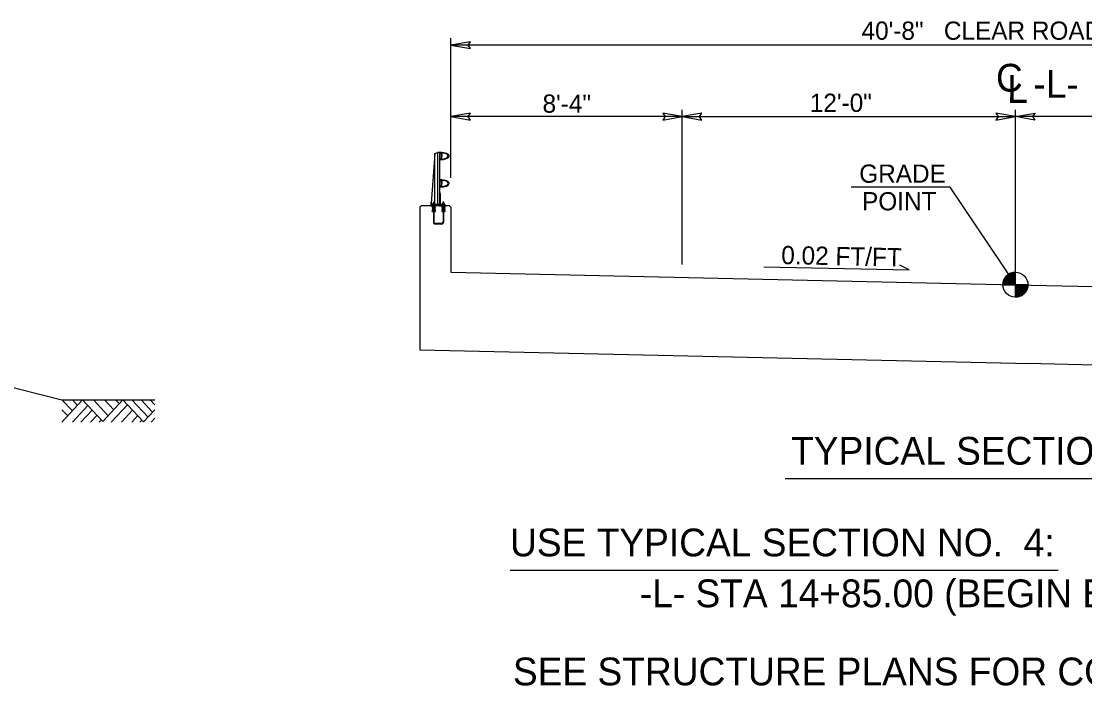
# Model space of a CAD drawing. Extents: x 1901984 to 1902132, y 194049 to 194156.
# Drawn here: x 1902050.33 to 1902088.64, y 194131.76 to 194155.68 of the extents above; entities that cross this region are included whole.
import ezdxf

# ---------------------------------------------------------------- set-up
doc = ezdxf.new("R2010")
doc.units = 0
for name, color, linetype in [('Old_Level_1', 7, 'Continuous'), ('Old_Level_11', 7, 'Continuous'), ('Old_Level_2', 7, 'Continuous'), ('Old_Level_3', 7, 'Continuous'), ('Scratch_Level_3', 7, 'Continuous'), ('Sheet PE Seal Cell', 7, 'Continuous')]:
    doc.layers.add(name, color=color, linetype=linetype)

# ---------------------------------------------------------------- blocks, each defined once
blk = doc.blocks.new('TERMINATOR')
at = {"layer": 'Scratch_Level_3'}
blk.add_lwpolyline([(-0.469, 0.081), (0, 0), (-0.471, -0.083), (-0.411, 0)], close=True, dxfattribs=at)

msp = doc.modelspace()

# ---------------------------------------------------------------- linework, layer by layer
at = {"layer": 'Old_Level_1'}
for p, q in [((1902065.811, 194150.049), (1902065.811, 194155.073)), ((1902106.478, 194154.823), (1902065.811, 194154.823)), ((1902074.144, 194146.923), (1902074.144, 194152.498)), ((1902086.144, 194146.196), (1902086.144, 194152.498)), ((1902074.144, 194152.249), (1902065.811, 194152.249)), ((1902074.144, 194152.248), (1902086.144, 194152.248)), ((1902098.144, 194152.248), (1902086.144, 194152.248)), ((1902064.693, 194146.673), (1902064.693, 194143.855)), ((1902065.811, 194146.648), (1902086.144, 194146.196)), ((1902077.081, 194146.843), (1902082.314, 194146.738)), ((1902082.314, 194146.738), (1902081.981, 194146.905)), ((1902086.144, 194146.196), (1902086.144, 194146.646)), ((1902085.694, 194146.196), (1902086.144, 194146.196)), ((1902086.145, 194145.746), (1902086.144, 194146.196)), ((1902086.594, 194146.196), (1902086.144, 194146.196)), ((1902086.144, 194146.196), (1902086.145, 194145.746)), ((1902086.144, 194146.196), (1902106.478, 194145.745)), ((1902039.554, 194145.116), (1902051.797, 194142.055)), ((1902064.693, 194143.855), (1902086.689, 194143.366)), ((1902086.563, 194143.369), (1902107.596, 194142.901))]:
    msp.add_line(p, q, dxfattribs=at)
for points in [[(1902085.978, 194146.614), (1902085.978, 194146.196)], [(1902085.987, 194146.618), (1902085.987, 194146.196)], [(1902085.996, 194146.621), (1902085.996, 194146.196)], [(1902086.005, 194146.624), (1902086.005, 194146.196)], [(1902086.014, 194146.627), (1902086.014, 194146.196)], [(1902086.023, 194146.629), (1902086.023, 194146.196)], [(1902086.032, 194146.632), (1902086.032, 194146.196)], [(1902086.041, 194146.634), (1902086.041, 194146.196)], [(1902086.05, 194146.636), (1902086.05, 194146.196)], [(1902086.059, 194146.638), (1902086.059, 194146.196)], [(1902086.068, 194146.64), (1902086.068, 194146.196)], [(1902086.077, 194146.641), (1902086.077, 194146.196)], [(1902086.086, 194146.642), (1902086.086, 194146.196)], [(1902086.095, 194146.643), (1902086.095, 194146.196)], [(1902086.104, 194146.644), (1902086.104, 194146.196)], [(1902086.113, 194146.645), (1902086.113, 194146.196)], [(1902086.122, 194146.645), (1902086.122, 194146.196)], [(1902086.131, 194146.646), (1902086.131, 194146.196)], [(1902086.14, 194146.646), (1902086.14, 194146.646), (1902086.14, 194146.196)], [(1902085.699, 194146.26), (1902085.699, 194146.196)], [(1902085.708, 194146.306), (1902085.708, 194146.196)], [(1902085.717, 194146.337), (1902085.717, 194146.196)], [(1902085.726, 194146.362), (1902085.726, 194146.196)], [(1902085.735, 194146.383), (1902085.735, 194146.196)], [(1902085.744, 194146.402), (1902085.744, 194146.196)], [(1902085.753, 194146.418), (1902085.753, 194146.196)], [(1902085.762, 194146.433), (1902085.762, 194146.196)], [(1902085.771, 194146.447), (1902085.771, 194146.196)], [(1902085.78, 194146.46), (1902085.78, 194146.196)], [(1902085.789, 194146.472), (1902085.789, 194146.196)], [(1902085.798, 194146.483), (1902085.798, 194146.196)], [(1902085.807, 194146.494), (1902085.807, 194146.196)], [(1902085.816, 194146.504), (1902085.816, 194146.196)], [(1902085.825, 194146.513), (1902085.825, 194146.196)], [(1902085.834, 194146.522), (1902085.834, 194146.196)], [(1902085.843, 194146.53), (1902085.843, 194146.196)], [(1902085.852, 194146.538), (1902085.852, 194146.196)], [(1902085.861, 194146.546), (1902085.861, 194146.196)], [(1902085.87, 194146.553), (1902085.87, 194146.196)], [(1902085.879, 194146.559), (1902085.879, 194146.196)], [(1902085.888, 194146.566), (1902085.888, 194146.196)], [(1902085.897, 194146.572), (1902085.897, 194146.196)], [(1902085.906, 194146.578), (1902085.906, 194146.196)], [(1902085.915, 194146.583), (1902085.915, 194146.196)], [(1902085.924, 194146.588), (1902085.924, 194146.196)], [(1902085.933, 194146.593), (1902085.933, 194146.196)], [(1902085.942, 194146.598), (1902085.942, 194146.196)], [(1902085.951, 194146.602), (1902085.951, 194146.196)], [(1902085.96, 194146.606), (1902085.96, 194146.196)], [(1902085.969, 194146.61), (1902085.969, 194146.196)], [(1902086.151, 194146.196), (1902086.151, 194145.746), (1902086.151, 194145.746)], [(1902086.16, 194146.196), (1902086.16, 194145.746)], [(1902086.169, 194146.196), (1902086.169, 194145.747)], [(1902086.178, 194146.196), (1902086.178, 194145.747)], [(1902086.187, 194146.196), (1902086.187, 194145.748)], [(1902086.196, 194146.196), (1902086.196, 194145.749)], [(1902086.205, 194146.196), (1902086.205, 194145.75)], [(1902086.214, 194146.196), (1902086.214, 194145.752)], [(1902086.223, 194146.196), (1902086.223, 194145.753)], [(1902086.232, 194146.196), (1902086.232, 194145.755)], [(1902086.241, 194146.196), (1902086.241, 194145.757)], [(1902086.25, 194146.196), (1902086.25, 194145.759)], [(1902086.259, 194146.196), (1902086.259, 194145.761)], [(1902086.268, 194146.196), (1902086.268, 194145.764)], [(1902086.277, 194146.196), (1902086.277, 194145.766)], [(1902086.286, 194146.196), (1902086.286, 194145.769)], [(1902086.295, 194146.196), (1902086.295, 194145.772)], [(1902086.304, 194146.196), (1902086.304, 194145.775)], [(1902086.313, 194146.196), (1902086.313, 194145.779)], [(1902086.322, 194146.196), (1902086.322, 194145.783)], [(1902086.331, 194146.196), (1902086.331, 194145.787)], [(1902086.34, 194146.196), (1902086.34, 194145.791)], [(1902086.349, 194146.196), (1902086.349, 194145.795)], [(1902086.358, 194146.196), (1902086.358, 194145.8)], [(1902086.367, 194146.196), (1902086.367, 194145.805)], [(1902086.376, 194146.196), (1902086.376, 194145.81)], [(1902086.385, 194146.196), (1902086.385, 194145.816)], [(1902086.394, 194146.196), (1902086.394, 194145.822)], [(1902086.403, 194146.196), (1902086.403, 194145.828)], [(1902086.412, 194146.196), (1902086.412, 194145.834)], [(1902086.421, 194146.196), (1902086.421, 194145.841)], [(1902086.43, 194146.196), (1902086.43, 194145.848)], [(1902086.439, 194146.196), (1902086.439, 194145.856)], [(1902086.448, 194146.196), (1902086.448, 194145.864)], [(1902086.457, 194146.196), (1902086.457, 194145.872)], [(1902086.466, 194146.196), (1902086.466, 194145.881)], [(1902086.475, 194146.196), (1902086.475, 194145.891)], [(1902086.484, 194146.196), (1902086.484, 194145.901)], [(1902086.493, 194146.196), (1902086.493, 194145.912)], [(1902086.502, 194146.196), (1902086.502, 194145.923)], [(1902086.511, 194146.196), (1902086.511, 194145.935)], [(1902086.52, 194146.196), (1902086.52, 194145.948)], [(1902086.529, 194146.196), (1902086.529, 194145.962)], [(1902086.538, 194146.196), (1902086.538, 194145.978)], [(1902086.547, 194146.196), (1902086.547, 194145.995)], [(1902086.556, 194146.196), (1902086.556, 194146.014)], [(1902086.565, 194146.196), (1902086.565, 194146.035)], [(1902086.574, 194146.196), (1902086.574, 194146.062)], [(1902086.583, 194146.196), (1902086.583, 194146.094)], [(1902086.592, 194146.196), (1902086.592, 194146.147)], [(1902051.797, 194142.055), (1902055.139, 194142.055)]]:
    msp.add_lwpolyline(points, dxfattribs=at)
msp.add_circle((1902086.145, 194146.196), 0.45, dxfattribs=at)
for start, end in [(90.0095, 180.0095), (270.0095, 0.0095)]:
    msp.add_arc((1902086.145, 194146.196), 0.45, start, end, dxfattribs=at)
at = {"layer": 'Old_Level_11'}
for p, q in [((1902051.797, 194142.055), (1902052.172, 194141.652)), ((1902051.797, 194141.25), (1902052.539, 194142.047)), ((1902052.172, 194142.055), (1902052.359, 194141.854)), ((1902052.539, 194142.047), (1902053.263, 194141.268)), ((1902052.93, 194142.055), (1902053.463, 194141.482)), ((1902053.263, 194141.268), (1902053.994, 194142.054)), ((1902053.328, 194142.055), (1902053.661, 194141.696)), ((1902053.73, 194142.055), (1902053.863, 194141.912)), ((1902053.994, 194142.054), (1902054.735, 194141.258)), ((1902054.316, 194142.055), (1902054.896, 194141.432)), ((1902054.649, 194142.055), (1902055.063, 194141.611)), ((1902054.969, 194142.055), (1902055.139, 194141.872)), ((1902051.797, 194141.693), (1902052.003, 194141.471)), ((1902052.171, 194141.25), (1902052.725, 194141.846)), ((1902052.48, 194141.25), (1902052.881, 194141.679)), ((1902053.573, 194141.25), (1902054.159, 194141.878)), ((1902053.943, 194141.25), (1902054.343, 194141.679)), ((1902054.735, 194141.258), (1902055.139, 194141.693)), ((1902052.827, 194141.25), (1902053.054, 194141.493)), ((1902053.138, 194141.25), (1902053.209, 194141.326)), ((1902054.309, 194141.25), (1902054.526, 194141.483)), ((1902054.604, 194141.25), (1902054.673, 194141.324)), ((1902055.005, 194141.25), (1902055.139, 194141.393)), ((1902077.852, 194139.224), (1902094.478, 194139.224)), ((1902067.938, 194135.923), (1902087.682, 194135.923))]:
    msp.add_line(p, q, dxfattribs=at)
at = {"layer": 'Old_Level_3'}
for q in [(1902080.229, 194149.711), (1902086.144, 194146.196)]:
    msp.add_line((1902083.786, 194149.711), q, dxfattribs=at)
at = {"layer": 'Sheet PE Seal Cell'}
for p, q in [((1902065.223, 194150.926), (1902065.092, 194149.117)), ((1902065.223, 194150.926), (1902065.337, 194150.963)), ((1902065.223, 194149.08), (1902065.223, 194150.926)), ((1902065.412, 194150.963), (1902065.337, 194150.963)), ((1902065.337, 194149.08), (1902065.337, 194150.963)), ((1902065.412, 194149.08), (1902065.412, 194150.963)), ((1902065.475, 194150.932), (1902065.475, 194150.83)), ((1902065.475, 194150.727), (1902065.475, 194150.83)), ((1902065.223, 194150.062), (1902065.219, 194150.062)), ((1902065.475, 194149.945), (1902065.475, 194149.843)), ((1902065.475, 194149.74), (1902065.475, 194149.843)), ((1902064.693, 194148.993), (1902064.742, 194149.042)), ((1902064.693, 194148.993), (1902064.693, 194146.673)), ((1902065.762, 194149.042), (1902064.742, 194149.042)), ((1902065.092, 194149.08), (1902065.092, 194149.117)), ((1902065.095, 194149.138), (1902065.095, 194149.171)), ((1902065.235, 194149.006), (1902065.135, 194149.006)), ((1902065.235, 194148.995), (1902065.135, 194148.995)), ((1902065.177, 194148.961), (1902065.135, 194148.961)), ((1902065.177, 194148.95), (1902065.135, 194148.95)), ((1902065.177, 194148.917), (1902065.135, 194148.917)), ((1902065.177, 194148.983), (1902065.157, 194148.983)), ((1902065.177, 194148.972), (1902065.157, 194148.972)), ((1902065.177, 194148.939), (1902065.157, 194148.939)), ((1902065.177, 194148.928), (1902065.157, 194148.928)), ((1902065.164, 194148.996), (1902065.164, 194149.08)), ((1902065.208, 194149.156), (1902065.165, 194149.156)), ((1902065.165, 194149.156), (1902065.165, 194149.12)), ((1902065.193, 194148.984), (1902065.177, 194148.984)), ((1902065.177, 194148.984), (1902065.177, 194148.453)), ((1902065.193, 194148.984), (1902065.193, 194148.453)), ((1902065.213, 194148.983), (1902065.193, 194148.983)), ((1902065.213, 194148.972), (1902065.193, 194148.972)), ((1902065.235, 194148.961), (1902065.193, 194148.961)), ((1902065.235, 194148.95), (1902065.193, 194148.95)), ((1902065.213, 194148.939), (1902065.193, 194148.939)), ((1902065.213, 194148.928), (1902065.193, 194148.928)), ((1902065.235, 194148.917), (1902065.193, 194148.917)), ((1902065.208, 194149.12), (1902065.208, 194149.156)), ((1902065.208, 194148.996), (1902065.208, 194149.08)), ((1902065.584, 194149.006), (1902065.483, 194149.006)), ((1902065.584, 194148.995), (1902065.483, 194148.995)), ((1902065.525, 194148.961), (1902065.483, 194148.961)), ((1902065.525, 194148.95), (1902065.483, 194148.95)), ((1902065.525, 194148.917), (1902065.483, 194148.917)), ((1902065.525, 194148.983), (1902065.506, 194148.983)), ((1902065.525, 194148.972), (1902065.506, 194148.972)), ((1902065.525, 194148.939), (1902065.506, 194148.939)), ((1902065.525, 194148.928), (1902065.506, 194148.928)), ((1902065.512, 194149.006), (1902065.512, 194149.089)), ((1902065.557, 194149.166), (1902065.514, 194149.166)), ((1902065.514, 194149.166), (1902065.514, 194149.13)), ((1902065.525, 194148.984), (1902065.525, 194148.453)), ((1902065.542, 194148.983), (1902065.525, 194148.983)), ((1902065.542, 194148.984), (1902065.542, 194148.453)), ((1902065.562, 194148.983), (1902065.542, 194148.983)), ((1902065.562, 194148.972), (1902065.542, 194148.972)), ((1902065.584, 194148.961), (1902065.542, 194148.961)), ((1902065.584, 194148.95), (1902065.542, 194148.95)), ((1902065.562, 194148.939), (1902065.542, 194148.939)), ((1902065.562, 194148.928), (1902065.542, 194148.928)), ((1902065.584, 194148.917), (1902065.542, 194148.917)), ((1902065.557, 194149.13), (1902065.557, 194149.166)), ((1902065.559, 194149.006), (1902065.559, 194149.089)), ((1902065.762, 194149.042), (1902065.811, 194148.993)), ((1902065.811, 194148.993), (1902065.811, 194146.648)), ((1902065.177, 194148.906), (1902065.135, 194148.906)), ((1902065.177, 194148.873), (1902065.135, 194148.873)), ((1902065.177, 194148.861), (1902065.135, 194148.861)), ((1902065.177, 194148.828), (1902065.135, 194148.828)), ((1902065.177, 194148.817), (1902065.135, 194148.817)), ((1902065.177, 194148.895), (1902065.157, 194148.895)), ((1902065.177, 194148.884), (1902065.157, 194148.884)), ((1902065.177, 194148.85), (1902065.157, 194148.85)), ((1902065.177, 194148.839), (1902065.157, 194148.839)), ((1902065.235, 194148.906), (1902065.193, 194148.906)), ((1902065.213, 194148.895), (1902065.193, 194148.895)), ((1902065.213, 194148.884), (1902065.193, 194148.884)), ((1902065.235, 194148.873), (1902065.193, 194148.873)), ((1902065.235, 194148.861), (1902065.193, 194148.861)), ((1902065.213, 194148.85), (1902065.193, 194148.85)), ((1902065.213, 194148.839), (1902065.193, 194148.839)), ((1902065.235, 194148.828), (1902065.193, 194148.828)), ((1902065.235, 194148.817), (1902065.193, 194148.817)), ((1902065.525, 194148.906), (1902065.483, 194148.906)), ((1902065.525, 194148.873), (1902065.483, 194148.873)), ((1902065.525, 194148.861), (1902065.483, 194148.861)), ((1902065.525, 194148.828), (1902065.483, 194148.828)), ((1902065.525, 194148.817), (1902065.483, 194148.817)), ((1902065.525, 194148.895), (1902065.506, 194148.895)), ((1902065.525, 194148.884), (1902065.506, 194148.884)), ((1902065.525, 194148.85), (1902065.506, 194148.85)), ((1902065.525, 194148.839), (1902065.506, 194148.839)), ((1902065.584, 194148.906), (1902065.542, 194148.906)), ((1902065.562, 194148.895), (1902065.542, 194148.895)), ((1902065.562, 194148.884), (1902065.542, 194148.884)), ((1902065.584, 194148.873), (1902065.542, 194148.873)), ((1902065.584, 194148.861), (1902065.542, 194148.861)), ((1902065.562, 194148.85), (1902065.542, 194148.85)), ((1902065.562, 194148.839), (1902065.542, 194148.839)), ((1902065.584, 194148.828), (1902065.542, 194148.828)), ((1902065.584, 194148.817), (1902065.542, 194148.817)), ((1902065.472, 194148.4), (1902065.247, 194148.4)), ((1902065.472, 194148.383), (1902065.247, 194148.383))]:
    msp.add_line(p, q, dxfattribs=at)
for points in [[(1902065.412, 194150.699), (1902065.412, 194150.748), (1902065.432, 194150.748), (1902065.432, 194150.74), (1902065.431, 194150.74), (1902065.431, 194150.719), (1902065.463, 194150.719), (1902065.467, 194150.751), (1902065.467, 194150.83), (1902065.467, 194150.908), (1902065.463, 194150.94), (1902065.431, 194150.94), (1902065.431, 194150.919), (1902065.432, 194150.919), (1902065.432, 194150.911), (1902065.412, 194150.911), (1902065.412, 194150.96)], [(1902065.412, 194149.712), (1902065.412, 194149.761), (1902065.432, 194149.761), (1902065.432, 194149.753), (1902065.431, 194149.753), (1902065.431, 194149.732), (1902065.463, 194149.732), (1902065.467, 194149.764), (1902065.467, 194149.843), (1902065.467, 194149.921), (1902065.463, 194149.952), (1902065.431, 194149.952), (1902065.431, 194149.932), (1902065.432, 194149.932), (1902065.432, 194149.924), (1902065.412, 194149.924), (1902065.412, 194149.973)], [(1902065.605, 194149.042), (1902065.605, 194149.089), (1902065.431, 194149.089), (1902065.431, 194149.476), (1902065.412, 194149.476), (1902065.412, 194149.08), (1902065.1, 194149.08), (1902065.1, 194149.107), (1902065.092, 194149.107), (1902065.092, 194149.042), (1902065.242, 194149.042), (1902065.242, 194149.068), (1902065.393, 194149.068), (1902065.393, 194149.042), (1902065.605, 194149.042)], [(1902065.135, 194149.006), (1902065.135, 194148.995), (1902065.157, 194148.983), (1902065.157, 194148.972), (1902065.135, 194148.961), (1902065.135, 194148.95), (1902065.157, 194148.939), (1902065.157, 194148.928), (1902065.135, 194148.917), (1902065.135, 194148.906), (1902065.157, 194148.895), (1902065.157, 194148.884), (1902065.135, 194148.873), (1902065.135, 194148.861), (1902065.157, 194148.85), (1902065.157, 194148.839), (1902065.135, 194148.828), (1902065.135, 194148.817)], [(1902065.229, 194149.079), (1902065.229, 194149.088), (1902065.186, 194149.088), (1902065.143, 194149.088), (1902065.143, 194149.079)], [(1902065.218, 194149.088), (1902065.218, 194149.115), (1902065.213, 194149.12), (1902065.16, 194149.12), (1902065.154, 194149.115), (1902065.154, 194149.088), (1902065.218, 194149.088), (1902065.197, 194149.088), (1902065.197, 194149.115), (1902065.202, 194149.12), (1902065.197, 194149.115), (1902065.192, 194149.12), (1902065.181, 194149.12), (1902065.175, 194149.115), (1902065.175, 194149.088), (1902065.175, 194149.115), (1902065.17, 194149.12)], [(1902065.235, 194149.006), (1902065.235, 194148.995), (1902065.213, 194148.983), (1902065.213, 194148.972), (1902065.235, 194148.961), (1902065.235, 194148.95), (1902065.213, 194148.939), (1902065.213, 194148.928), (1902065.235, 194148.917), (1902065.235, 194148.906), (1902065.213, 194148.895), (1902065.213, 194148.884), (1902065.235, 194148.873), (1902065.235, 194148.861), (1902065.213, 194148.85), (1902065.213, 194148.839), (1902065.235, 194148.828), (1902065.235, 194148.817)], [(1902065.483, 194149.006), (1902065.483, 194148.995), (1902065.506, 194148.983), (1902065.506, 194148.972), (1902065.483, 194148.961), (1902065.483, 194148.95), (1902065.506, 194148.939), (1902065.506, 194148.928), (1902065.483, 194148.917), (1902065.483, 194148.906), (1902065.506, 194148.895), (1902065.506, 194148.884), (1902065.483, 194148.873), (1902065.483, 194148.861), (1902065.506, 194148.85), (1902065.506, 194148.839), (1902065.483, 194148.828), (1902065.483, 194148.817)], [(1902065.579, 194149.089), (1902065.579, 194149.097), (1902065.536, 194149.097), (1902065.493, 194149.097), (1902065.493, 194149.089)], [(1902065.567, 194149.097), (1902065.567, 194149.124), (1902065.562, 194149.13), (1902065.509, 194149.13), (1902065.503, 194149.124), (1902065.503, 194149.097), (1902065.567, 194149.097), (1902065.546, 194149.097), (1902065.546, 194149.124), (1902065.551, 194149.13), (1902065.546, 194149.124), (1902065.54, 194149.13), (1902065.529, 194149.13), (1902065.524, 194149.124), (1902065.524, 194149.097), (1902065.524, 194149.124), (1902065.519, 194149.13)], [(1902065.584, 194149.006), (1902065.584, 194148.995), (1902065.562, 194148.983), (1902065.562, 194148.972), (1902065.584, 194148.961), (1902065.584, 194148.95), (1902065.562, 194148.939), (1902065.562, 194148.928), (1902065.584, 194148.917), (1902065.584, 194148.906), (1902065.562, 194148.895), (1902065.562, 194148.884), (1902065.584, 194148.873), (1902065.584, 194148.861), (1902065.562, 194148.85), (1902065.562, 194148.839), (1902065.584, 194148.828), (1902065.584, 194148.817)]]:
    msp.add_lwpolyline(points, dxfattribs=at)
for centre in [(1902065.144, 194148.845), (1902065.575, 194148.845)]:
    msp.add_circle(centre, 0.00834, dxfattribs=at)
for centre, radius, start, end in [((1902065.483, 194150.932), 0.00783, 90, 180), ((1902065.483, 194150.727), 0.00783, 180, 270), ((1902065.483, 194149.945), 0.00783, 90, 180), ((1902065.483, 194149.74), 0.00783, 180, 270), ((1902065.247, 194148.453), 0.07, 180, 270), ((1902065.247, 194148.453), 0.0534, 180, 270), ((1902065.472, 194148.453), 0.0534, 270, 0), ((1902065.472, 194148.453), 0.07, 270, 0)]:
    msp.add_arc(centre, radius, start, end, dxfattribs=at)
for centre, major_axis, ratio, start_param, end_param in [((1902065.412, 194150.83), (0.334, 0), 0.39036, 6.282787, 7.853967), ((1902065.412, 194150.83), (0.334, 0), 0.39036, 4.712404, 6.282787), ((1902065.483, 194150.83), (0.222, 0), 0.495501, 6.282718, 7.853881), ((1902065.483, 194150.83), (0.222, 0), 0.495501, 4.712489, 6.282718), ((1902065.412, 194149.842), (0.334, 0), 0.39036, 6.282787, 7.853967), ((1902065.412, 194149.842), (0.334, 0), 0.39036, 4.712404, 6.282787), ((1902065.483, 194149.842), (0.222, 0), 0.495501, 6.282718, 7.853881), ((1902065.483, 194149.842), (0.222, 0), 0.495501, 4.712489, 6.282718)]:
    msp.add_ellipse(centre, major_axis=major_axis, ratio=ratio, start_param=start_param, end_param=end_param, dxfattribs=at)

# ---------------------------------------------------------------- block references
at = {"layer": 'Old_Level_1', "xscale": 1.5, "rotation": 180}
for p, yscale in [((1902065.811, 194154.823), -1.5), ((1902065.811, 194152.249), -1.5), ((1902074.144, 194152.248), -1.5), ((1902086.144, 194152.248), 1.5)]:
    msp.add_blockref('TERMINATOR', p, dxfattribs=dict(at, yscale=yscale))
at = {"layer": 'Old_Level_1', "xscale": 1.5, "yscale": -1.5}
for p in [(1902074.144, 194152.249), (1902086.144, 194152.248)]:
    msp.add_blockref('TERMINATOR', p, dxfattribs=at)

# ---------------------------------------------------------------- texts
at = {"layer": 'Old_Level_1'}
for s, p in [('40\'-8"   CLEAR ROADWAY', (1902080.601, 194155.017)), ('8\'-4"', (1902069.109, 194152.39)), ('12\'-0" ', (1902078.738, 194152.42))]:
    msp.add_text(s, height=0.656, dxfattribs=at).set_placement(p)
at = {"layer": 'Old_Level_11'}
for s, height, p in [('GRADE', 0.656, (1902080.518, 194149.869)), ('POINT', 0.656, (1902080.619, 194148.875)), ('TYPICAL SECTION NO.  4', 1, (1902078.063, 194139.718)), ('USE TYPICAL SECTION NO.  4:', 1, (1902067.938, 194136.417)), ('-L- STA 14+85.00 (BEGIN BRIDGE) TO 16+75.00 (END BRIDGE)', 1, (1902072.614, 194134.585)), ('SEE STRUCTURE PLANS FOR CONSTRUCTION DETAILS', 1, (1902068.041, 194131.773))]:
    msp.add_text(s, height=height, dxfattribs=at).set_placement(p)
at = {"layer": 'Old_Level_2'}
msp.add_text('C', height=1, dxfattribs=at).set_placement((1902085.443, 194153.15))
for s, height, rotation, p in [('-L-', 1, 359.9469, (1902086.793, 194152.928)), ('L', 1, 359.9469, (1902085.845, 194152.746)), ('0.02 FT/FT', 0.656, 358.8656, (1902077.704, 194146.941))]:
    msp.add_text(s, height=height, rotation=rotation, dxfattribs=at).set_placement(p)

doc.saveas('drawing.dxf')
